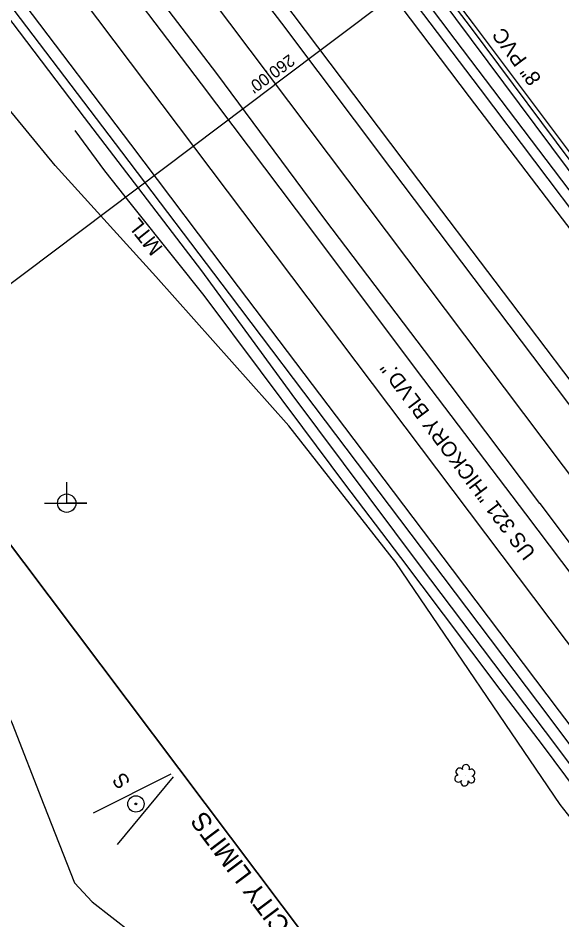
# Model space of a CAD drawing. Extents: x 1262092 to 1264624, y 774970 to 778314.
# Drawn here: x 1262309.6 to 1262454.7, y 777671.7 to 777912.2 of the extents above; entities that cross this region are included whole.
import ezdxf

# ---------------------------------------------------------------- set-up
doc = ezdxf.new("R2010")
doc.units = 0
for name, color, linetype in [('Exist Boundary City Limits', 7, 'Continuous'), ('Exist Boundary City Limits Text', 7, 'Continuous'), ('Exist Horizontal Alignment', 7, 'Continuous'), ('Exist Horizontal Alignment Station Label', 7, 'Continuous'), ('Exist Horizontal Alignment Tick Large', 7, 'Continuous'), ('Exist Right of Way Line', 7, 'Continuous'), ('Exist Right of Way Width CELL', 7, 'Continuous'), ('Exist Roads EOP', 7, 'Continuous'), ('Exist Roads EOP Text', 7, 'Continuous'), ('Exist Roads EOT', 7, 'Continuous'), ('Exist Structure Minor Pipes RCP 18 Inch', 7, 'Continuous'), ('Exist Utilities Gas UG Line SUE LOS B', 7, 'Continuous'), ('Exist Utilities Power Joint Use Telephone CELL', 7, 'Continuous'), ('Exist Utilities Sanitary Sewer UG Line', 7, 'Continuous'), ('Exist Utilities Sanitary Sewer UG Line Text', 7, 'Continuous'), ('Exist Utilities Telephone UG FO SUE LOS B', 7, 'Continuous'), ('Exist Utilities Water UG Line SUE LOS B', 7, 'Continuous'), ('Prop Conc 5in Monolithic Keyed In Island', 7, 'Continuous'), ('Prop Paved Shoulder', 7, 'Continuous'), ('Sheet Plan Layout CELL', 7, 'Continuous'), ('Typical Text Label CELL', 7, 'Continuous')]:
    doc.layers.add(name, color=color, linetype=linetype)

msp = doc.modelspace()

# ---------------------------------------------------------------- linework, layer by layer
at = {"layer": 'Exist Boundary City Limits'}
msp.add_line((1263013.39, 776834.66), (1262172.78, 777950.69), dxfattribs=at)
at = {"layer": 'Exist Horizontal Alignment'}
msp.add_line((1264460.35, 775084.79), (1262255.05, 778012.66), dxfattribs=at)
at = {"layer": 'Exist Horizontal Alignment Station Label'}
for p, q in [((1262350.35, 777710.53), (1262329.64, 777700.17)), ((1262336.18, 777691.77), (1262351.06, 777709.81))]:
    msp.add_line(p, q, dxfattribs=at)
for radius in [2.18, 0.24]:
    msp.add_circle((1262341.06, 777702.61), radius, dxfattribs=at)
at = {"layer": 'Exist Horizontal Alignment Tick Large'}
msp.add_line((1262428.84, 777710.06), (1262428.84, 777710.06), dxfattribs=at)
for centre, radius, start, end in [((1262427.36, 777711.19), 0.968, 35.8908, 245.4216), ((1262429.07, 777712.1), 0.99, 334.8391, 200.4717), ((1262430.51, 777710.93), 0.929, 284.4567, 126.0861), ((1262427.04, 777709.36), 0.955, 95.1099, 327.9534), ((1262430.48, 777709.13), 0.937, 204.9913, 73.4601), ((1262428.71, 777708.38), 0.984, 151.2797, 21.387)]:
    msp.add_arc(centre, radius, start, end, dxfattribs=at)
at = {"layer": 'Exist Right of Way Line'}
msp.add_line((1262172.78, 777950.69), (1263224.83, 776553.94), dxfattribs=at)
at = {"layer": 'Exist Right of Way Width CELL'}
for p in [(1262481.82, 777972.54), (1262274.14, 777816.12)]:
    msp.add_line(p, (1262377.95, 777894.31), dxfattribs=at)
at = {"layer": 'Exist Roads EOP'}
for points in [[(1262311.57, 778054.09), (1262320.31, 778042.27), (1262347.65, 778006.04), (1262376.01, 777968.97), (1262404.37, 777930.89), (1262432.91, 777893.24), (1262461.84, 777854.83), (1262490.86, 777816.65), (1262505.6, 777797.35)], [(1262285.77, 778035.09), (1262294.3, 778023.82), (1262322.73, 777986.32), (1262351.06, 777948.49), (1262379.86, 777910.83), (1262408.98, 777872.17), (1262437.51, 777834.34), (1262465.79, 777796.98), (1262494.21, 777759.25), (1262523.56, 777720.28), (1262551.17, 777683.56), (1262580.06, 777645.73)], [(1262533.86, 777669.85), (1262506.16, 777706.68), (1262477.25, 777744.96), (1262448.83, 777782.76), (1262448.77, 777782.75), (1262419.94, 777820.99), (1262391.44, 777858.59), (1262362.67, 777897.37), (1262333.74, 777935.31), (1262305.02, 777973.3), (1262276.84, 778010.82), (1262268.09, 778022.33)], [(1262508.59, 777649.5), (1262480.62, 777686.61), (1262451.55, 777725.45), (1262423.03, 777763.23), (1262394.37, 777801.14), (1262366.02, 777838.6), (1262337.3, 777876.52), (1262308.59, 777914.31), (1262279.57, 777952.95), (1262251.16, 777991.02), (1262242.02, 778002.99)]]:
    msp.add_lwpolyline(points, dxfattribs=at)
at = {"layer": 'Exist Roads EOT'}
for points in [[(1262308.34, 778051.79), (1262317.32, 778039.93), (1262344.37, 778004.19), (1262372.89, 777966.62), (1262401.21, 777929.2), (1262429.93, 777891.21), (1262458.73, 777853.38), (1262487.94, 777814.62), (1262517.12, 777776.18), (1262546.22, 777737.8), (1262573.92, 777700.82), (1262602.3, 777663.12)], [(1262289.2, 778037.57), (1262297.52, 778026.31), (1262325.76, 777988.99), (1262354.59, 777951.12), (1262382.95, 777913.24), (1262412.22, 777874.41), (1262440.97, 777836.5), (1262469.27, 777799.15), (1262497.42, 777761.79), (1262526.95, 777722.8), (1262554.72, 777686.15), (1262583.3, 777648.11)], [(1262530.21, 777667.14), (1262502.53, 777703.54), (1262473.57, 777742.17), (1262445.07, 777779.99), (1262416.17, 777818.02), (1262387.95, 777855.59), (1262358.59, 777894.64), (1262330.16, 777932.09), (1262301.01, 777970.53), (1262273.04, 778007.62), (1262264.28, 778019.28)], [(1262511.28, 777651.42), (1262483.32, 777688.89), (1262454.05, 777727.36), (1262425.45, 777765.13), (1262396.78, 777803.08), (1262368.42, 777840.5), (1262339.71, 777878.55), (1262311.54, 777915.71), (1262282.01, 777954.91), (1262253.58, 777992.51), (1262244.27, 778004.78)]]:
    msp.add_lwpolyline(points, dxfattribs=at)
at = {"layer": 'Exist Structure Minor Pipes RCP 18 Inch'}
msp.add_line((1262514.1, 777714.3), (1262275, 778031.81), dxfattribs=at)
at = {"layer": 'Exist Utilities Gas UG Line SUE LOS B'}
msp.add_lwpolyline([(1262994.39, 777166.73), (1262980.63, 777180.77), (1262951.12, 777219.34), (1262915.77, 777266.99), (1262883.3, 777310), (1262857.54, 777344.34), (1262828.14, 777381.91), (1262793.47, 777427.19), (1262760.54, 777472.85), (1262727.33, 777519.3), (1262694.08, 777555.83), (1262655.09, 777608.15), (1262623.1, 777653.3), (1262592.34, 777693.87), (1262575.48, 777722.21), (1262534.9, 777775.61), (1262497.72, 777820.92), (1262460.79, 777868.95), (1262430.33, 777909.82), (1262335.35, 778033.97), (1262366.66, 777994.16), (1262337.19, 778032.97), (1262314.26, 778062.88)], dxfattribs=at)
msp.add_lwpolyline([(1262994.39, 777166.73), (1262980.63, 777180.77), (1262951.12, 777219.34), (1262915.77, 777266.99), (1262883.3, 777310), (1262857.54, 777344.34), (1262828.14, 777381.91), (1262793.47, 777427.19), (1262760.54, 777472.85), (1262727.33, 777519.3), (1262694.08, 777555.83), (1262655.09, 777608.15), (1262623.1, 777653.3), (1262592.34, 777693.87), (1262575.48, 777722.21), (1262534.9, 777775.61), (1262497.72, 777820.92), (1262460.79, 777868.95), (1262430.33, 777909.82), (1262335.35, 778033.97), (1262366.66, 777994.16), (1262337.19, 778032.97), (1262314.26, 778062.88)], dxfattribs=at)
at = {"layer": 'Exist Utilities Power Joint Use Telephone CELL'}
msp.add_line((1262322.6, 777782.8), (1262322.6, 777782.8), dxfattribs=at)
msp.add_lwpolyline([(1262316.66, 777782.8), (1262328, 777782.77), (1262322.6, 777782.78), (1262322.6, 777788.43)], dxfattribs=at)
msp.add_circle((1262322.6, 777782.81), 2.45, dxfattribs=at)
at = {"layer": 'Exist Utilities Sanitary Sewer UG Line'}
msp.add_line((1262150.97, 778282.31), (1262537.27, 777762.91), dxfattribs=at)
at = {"layer": 'Exist Utilities Telephone UG FO SUE LOS B'}
for points in [[(1262989.94, 777168.07), (1262951.99, 777219.94), (1262916.42, 777267.81), (1262888.77, 777316.31), (1262864.92, 777351.47), (1262838.91, 777387.68), (1262799.61, 777432.02), (1262765.27, 777476.73), (1262731.32, 777522.28), (1262700.44, 777560.94), (1262661.97, 777612.3), (1262627.92, 777657.64), (1262612.11, 777680.33), (1262604.08, 777687.9), (1262594.67, 777695.7), (1262574.71, 777722.66), (1262534.65, 777775.25), (1262499.34, 777822.06), (1262462.07, 777869.42), (1262431.13, 777910.63), (1262336.58, 778034.92), (1262368.35, 777994.88), (1262338.32, 778033.37), (1262315.72, 778063.86)], [(1262989.94, 777168.07), (1262951.99, 777219.94), (1262916.42, 777267.81), (1262888.77, 777316.31), (1262864.92, 777351.47), (1262838.91, 777387.68), (1262799.61, 777432.02), (1262765.27, 777476.73), (1262731.32, 777522.28), (1262700.44, 777560.94), (1262661.97, 777612.3), (1262627.92, 777657.64), (1262612.11, 777680.33), (1262604.08, 777687.9), (1262594.67, 777695.7), (1262574.71, 777722.66), (1262534.65, 777775.25), (1262499.34, 777822.06), (1262462.07, 777869.42), (1262431.13, 777910.63), (1262336.58, 778034.92), (1262368.35, 777994.88), (1262338.32, 778033.37), (1262315.72, 778063.86)], [(1262982.78, 777167.11), (1262946.46, 777216.4), (1262911.63, 777263.89), (1262904.55, 777273.66), (1262904.75, 777279.08), (1262882.68, 777309.56), (1262855.72, 777342.59), (1262826.17, 777380.64), (1262792.14, 777426.47), (1262758.72, 777471.04), (1262724.36, 777517.1), (1262692.7, 777554.83), (1262654.13, 777607.32), (1262621.89, 777651.43), (1262589.79, 777691.14), (1262572.86, 777709.66), (1262527.82, 777770.05), (1262493.25, 777818.33), (1262456.6, 777866.38), (1262426.24, 777906.46), (1262391.81, 777952.18), (1262362.73, 777991.03), (1262332.92, 778030.12), (1262309.95, 778059.98)], [(1262497.69, 777644.72), (1262472.81, 777678.82), (1262454.22, 777702.45), (1262410.39, 777767.02), (1262381.85, 777803.45), (1262346.33, 777843.25), (1262319.52, 777872.83), (1262288.46, 777910.54), (1262263.91, 777943.64), (1262260.24, 777952.77), (1262251.56, 777965.81), (1262224.91, 778006.43)]]:
    msp.add_lwpolyline(points, dxfattribs=at)
at = {"layer": 'Exist Utilities Water UG Line SUE LOS B'}
msp.add_lwpolyline([(1262961.53, 777041.32), (1262916.91, 777099.45), (1262892.75, 777131.3), (1262862.6, 777171.1), (1262817.98, 777226.85), (1262789.55, 777268.74), (1262774.27, 777287.66), (1262763.83, 777305.05), (1262732.33, 777346.94), (1262685.88, 777410.11), (1262660.87, 777443.18), (1262632.31, 777481.08), (1262598.3, 777526.4), (1262560.14, 777576.52), (1262506.51, 777647.45), (1262479.01, 777683.48), (1262453.07, 777718.25), (1262416.94, 777766.02), (1262382.77, 777811.78), (1262358.61, 777844.73), (1262327.38, 777885.68), (1262302.32, 777918.54), (1262259.45, 777971.43), (1262223.66, 778020.3)], dxfattribs=at)
at = {"layer": 'Prop Conc 5in Monolithic Keyed In Island'}
msp.add_lwpolyline([(1262243.57, 777728.49), (1262247.11, 777740.03), (1262246.4, 777763.43), (1262240.71, 777781.37), (1262240.42, 777791.08), (1262244.13, 777820.23), (1262249.84, 777834.04), (1262254.54, 777834.16), (1262258.78, 777828.44), (1262269.13, 777805.64), (1262282.81, 777775.74), (1262295.35, 777751.2), (1262308.02, 777724.09), (1262316.51, 777702.39), (1262324.71, 777681.54), (1262329.36, 777676.47), (1262339.85, 777668.31)], dxfattribs=at)
at = {"layer": 'Typical Text Label CELL'}
for points in [[(1262449.46, 777718.32), (1262438.2, 777733.16), (1262423.09, 777753.21), (1262411.75, 777768.32), (1262396.74, 777788), (1262385.53, 777803), (1262374.25, 777818.1), (1262359.27, 777838.17), (1262351.51, 777847.86), (1262339.87, 777862.46), (1262332.8, 777871.48), (1262324.84, 777882.21)], [(1262768.2, 777292.26), (1262757.43, 777308.58), (1262750.97, 777317.87), (1262727.73, 777348.88), (1262712, 777369.55), (1262697.36, 777389.13), (1262675.04, 777418.88), (1262656.25, 777443.92), (1262630.05, 777478.82), (1262611.34, 777503.87), (1262588.61, 777533.8), (1262569.91, 777558.5), (1262554.82, 777578.68), (1262539.79, 777598.72), (1262516.99, 777628.51), (1262502.14, 777648.38), (1262483.36, 777673.29), (1262468.18, 777693.3), (1262449.46, 777718.32)]]:
    msp.add_lwpolyline(points, dxfattribs=at)

# ---------------------------------------------------------------- texts
at = {"layer": 'Exist Boundary City Limits Text'}
msp.add_text('HUDSON CITY LIMITS', height=5, rotation=126.9874, dxfattribs=at).set_placement((1262401.06, 777645.54))
at = {"layer": 'Exist Right of Way Width CELL'}
msp.add_text("260.00'", height=3.2, rotation=216.1518, dxfattribs=at).set_placement((1262381.94, 777902.68))
at = {"layer": 'Exist Roads EOP Text'}
msp.add_text('US 321 "HICKORY BLVD." ', height=4, rotation=126.9746, dxfattribs=at).set_placement((1262447.87, 777769.62))
at = {"layer": 'Exist Utilities Sanitary Sewer UG Line Text'}
msp.add_text('8" PVC', height=4, rotation=126.6401, dxfattribs=at).set_placement((1262449.35, 777896.08))
at = {"layer": 'Prop Paved Shoulder'}
msp.add_text('S', height=4, rotation=126.9874, dxfattribs=at).set_placement((1262339.79, 777708.5))
at = {"layer": 'Sheet Plan Layout CELL'}
msp.add_text(' MTL', height=4, rotation=128.5844, dxfattribs=at).set_placement((1262349.36, 777849.76))

doc.saveas('drawing.dxf')
